(* Logix 5000 project; controller ZaxisVmpEdsSample 1769-L16ER-BB1B rev 30.11; software revision 30.00 *)

TASK MainTask (continuous, watchdog 500 ms) : MainProgram

MODULES
   Local : 1769-L16ER-BB1B (PointIO 0, rev 30.11)
      VMP_01 : vendor 1449 type 43 code 17 (Ethernet 192.168.1.193, rev 1.1, StandardDataDriven RPI 20 ms)
      VMP_02 : vendor 1449 type 43 code 17 (Ethernet 192.168.1.146, rev 1.1, StandardDataDriven RPI 20 ms)
      VMP_03 : vendor 1449 type 43 code 17 (Ethernet 192.168.1.232, rev 1.1, StandardDataDriven RPI 20 ms)
      Discrete_IO : Embedded (PointIO 1, rev 30.11, Output RPI 20 ms)
           Local:1:I.Data.0   // Green Push Btn
           Local:1:I.Data.1   // Red Push Btn
           Local:1:I   // Green Btn #2
           Local:1:O   // Green Run Light
END_MODULES

TYPE DeepSetup :
STRUCT
   Bore : REAL;   // Bore
   Gain : REAL;   // Gain
   SphericalBearing : REAL[9];   // SphericalBearing
   MotorType : DINT;   // MotorType
   PumpType : DINT;   // PumpType
   PumpNumber : DINT;   // PumpNumber
   ReadyInterlock : DINT;   // RdyInputEnabled
   HoldOnFault : DINT;   // HoldOnFault
   EthernetRunReady : DINT;   // EthSendBusy
   Triple : DINT;   // Triple
   IpDHCP : DINT;   // IpDHCP
   PumpIdentiyNumb : SINT[24];   // PumpIdentityNumber
   PumpOptions : SINT[24];   // PumpOptions
   IpAddress : SINT[16];   // IpAddress
   IpNetMask : SINT[16];   // IpNetMask
   IpGateway : SINT[16];   // IpGateWay
   SerialNumber : SINT[16];   // SerialNumber
END_STRUCT
END_TYPE

TYPE VMP_Prg :
STRUCT
   CalDispenseTime : BOOL;   // CalDispenseTime
   Direction : BOOL;   // Direction CCW
   SetShotSize : BOOL;   // Set Volume
   ContinuousRun : BOOL;   // Run Continuously
   Spare1_4 : BOOL;   // Spare Bit
   Spare1_5 : BOOL;   // Spare Bit
   Spare1_6 : BOOL;   // Spare Bit
   Spare1_7 : BOOL;   // Spare Bit
   Spare1_8 : BOOL;   // Spare Bit
   Spare1_9 : BOOL;   // Spare Bit
   Spare1_10 : BOOL;   // Spare Bit
   Spare1_11 : BOOL;   // Spare Bit
   Spare1_12 : BOOL;   // Spare Bit
   Spare1_13 : BOOL;   // Spare Bit
   Spare1_14 : BOOL;   // Spare Bit
   Spare1_15 : BOOL;   // Spare Bit
   Spare1_16 : BOOL;   // Spare Bit
   Spare1_17 : BOOL;   // Spare Bit
   Spare1_18 : BOOL;   // Spare Bit
   Spare1_19 : BOOL;   // Spare Bit
   Spare1_20 : BOOL;   // Spare Bit
   Spare1_21 : BOOL;   // Spare Bit
   Spare1_22 : BOOL;   // Spare Bit
   Spare1_23 : BOOL;   // Spare Bit
   Spare1_24 : BOOL;   // Spare Bit
   Spare1_25 : BOOL;   // Spare Bit
   Spare1_26 : BOOL;   // Spare Bit
   Spare1_27 : BOOL;   // Spare Bit
   Spare1_28 : BOOL;   // Spare Bit
   Spare1_29 : BOOL;   // Spare Bit
   Spare1_30 : BOOL;   // Spare Bit
   Spare1_31 : BOOL;   // Spare Bit
   Program : DINT;   // Program
   PullBack : DINT;   // PullBack
   InitialRPM : DINT;   // InitialRPM
   RPM : DINT;   // RPM
   FinalRPM : DINT;   // FinalRPM
   FineAdjust : DINT;   // FineAdjust
   Acceleration : DINT;   // Acceleration
   Deceleration : DINT;   // Deceleration
   LoopCycles : DINT;   // LoopCycles
   LinkedProgram : DINT;   // LinkedProgram
   LinkedTimeDelay : DINT;   // LinkedTimeDelay
   MotorCurrent : DINT;   // MotorCurrent
   Revolutions : DINT;   // Revolutions
   AprxDispenseTime : DINT;   // DispenseTime
   Volume : REAL;   // Volume
   ProgramName : STRING;   // ProgramName
END_STRUCT
END_TYPE

TYPE VMP_Setup :
STRUCT
   ReadyInterlock : BOOL;   // RdyInputEnabled
   EthernetRunReady : BOOL;   // EthSendBusy
   HoldOnFault : BOOL;   // HoldOnFault
   Spare1_3 : BOOL;   // Spare Bit
   Spare1_4 : BOOL;   // Spare Bit
   Spare1_5 : BOOL;   // Spare Bit
   Spare1_6 : BOOL;   // Spare Bit
   Spare1_7 : BOOL;   // Spare Bit
   Spare1_8 : BOOL;   // Spare Bit
   Spare1_9 : BOOL;   // Spare Bit
   Spare1_10 : BOOL;   // Spare Bit
   Spare1_11 : BOOL;   // Spare Bit
   Spare1_12 : BOOL;   // Spare Bit
   Spare1_13 : BOOL;   // Spare Bit
   Spare1_14 : BOOL;   // Spare Bit
   Spare1_15 : BOOL;   // Spare Bit
   Spare1_16 : BOOL;   // Spare Bit
   Spare1_17 : BOOL;   // Spare Bit
   Spare1_18 : BOOL;   // Spare Bit
   Spare1_19 : BOOL;   // Spare Bit
   Spare1_20 : BOOL;   // Spare Bit
   Spare1_21 : BOOL;   // Spare Bit
   Spare1_22 : BOOL;   // Spare Bit
   Spare1_23 : BOOL;   // Spare Bit
   Spare1_24 : BOOL;   // Spare Bit
   Spare1_25 : BOOL;   // Spare Bit
   Spare1_26 : BOOL;   // Spare Bit
   Spare1_27 : BOOL;   // Spare Bit
   Spare1_28 : BOOL;   // Spare Bit
   Spare1_29 : BOOL;   // Spare Bit
   Spare1_30 : BOOL;   // Spare Bit
   Spare1_31 : BOOL;   // Spare Bit
   Baud : DINT;   // Baud
   PumpNumber : DINT;   // PumpNumber
   SpareDInt0 : DINT;   // SpareDInt0
   SpareDInt1 : DINT;   // SpareDInt1
   FirmwareRev : REAL;   // FirmRev
   Bore : REAL;   // Bore
   SpareReal0 : REAL;   // SpareReal0
   SpareReal1 : REAL;   // SpareReal1
   SerialNumber : STRING;   // SerialNumber
END_STRUCT
END_TYPE

TYPE VMP_TcpIP_Cfg :
STRUCT
   Status : DINT;   // Status
   Config_Capability : DINT;   // Capability
   Config_Control : DINT;   // IfCtrl
   Path_Size : INT;   // Epath
   Path : SINT[4];   // Padd
   IP_Address : DINT;   // IPAddr
   Network_Address : DINT;   // NetAddr
   Gateway_Address : DINT;   // GateWay
   Name_Server : DINT;   // DNS1
   Name_Server_2 : DINT;   // DNS2
   Domain_Name : STRING;   // Domain
   Host_Name : STRING;   // Host
   Safety_Network_Number : SINT[6];   // Ignore
   TTL : SINT;   // TTL
   Alloc_Control : SINT;   // MultCast
   Reserved : SINT;   // Reserved
   Num_Mcast : INT;   // MultCastAlloc
   Mcast_Start_Addr : DINT;   // MultCastStart
   Selected_Acd : BOOL;   // ACD
   Acd_Activity : SINT;   // ACDState
   Remote_MAC : SINT[6];   // MACRmt
   Arp_Pdu : SINT[28];   // ARP_PDU
   EthernetIP_Quick_Connect : BOOL;   // QuickCon
   Encp_Inactivity_Timeout : INT;   // InactTimeout
END_STRUCT
END_TYPE

VAR_GLOBAL   (* controller tags *)
   Deep_Setup : DeepSetup;
   Read_Deep_Setup : BOOL;
   ReadDeepSetup : MESSAGE;
        MessageParameters(ServiceCode := 16#0001, DestinationTag := Deep_Setup, ...)
   ReadPrg : MESSAGE;
        MessageParameters(ServiceCode := 16#0001, DestinationTag := VMP_Program, ...)
   ReadSetup : MESSAGE;
        MessageParameters(ServiceCode := 16#0001, DestinationTag := VMP_Setup, ...)
   ReadTcpIp : MESSAGE;
        MessageParameters(ServiceCode := 16#0001, DestinationTag := VMP_TcpIp_Cfg, ...)
   VMP_Config : VMP_Setup;
   VMP_Program : VMP_Prg := (InitialRPM := 130, RPM := 200, FinalRPM := 130, Acceleration := 90, Deceleration := 200, LoopCycles := 1, LinkedProgram := -1, MotorCurrent := 80, AprxDispenseTime := 310, Volume := 0.1036815, ProgramName := 'Program 00');
   VMP_Setup : VMP_Setup := (Baud := 1152, PumpNumber := 1, FirmwareRev := 1.3, Bore := 0.25, SerialNumber := '123-17V3');
   VMP_TcpIp_Cfg : VMP_TcpIP_Cfg := (Status := 16#0000_0001, Config_Capability := 16#0000_0034, Path_Size := 3, Path[0] := 16#f6, Path[2] := 16#24, Path[3] := 16#01, IP_Address := 16#c0a8_a866, Network_Address := 16#ffff_ff00, Gateway_Address := 16#c0a8_0101);
   VMP_TcpIp_Read : BOOL;
   VMP_TcpIp_Write : BOOL;
   WriteDeepSetup : MESSAGE;
        MessageParameters(ServiceCode := 16#0002, LocalElement := Deep_Setup, ...)
   WritePrg : MESSAGE;
        MessageParameters(ServiceCode := 16#0002, LocalElement := VMP_Program, ...)
   WritePrg_02 : MESSAGE;
        MessageParameters(ServiceCode := 16#0002, LocalElement := VMP_Program, ...)
   WritePrg_03 : MESSAGE;
        MessageParameters(ServiceCode := 16#0002, LocalElement := VMP_Setup, ...)
   WriteSetup : MESSAGE;
        MessageParameters(ServiceCode := 16#0002, LocalElement := VMP_Setup, ...)
   WriteSetup_02 : MESSAGE;
        MessageParameters(ServiceCode := 16#0002, LocalElement := VMP_Setup, ...)
   WriteSetup_03 : MESSAGE;
        MessageParameters(ServiceCode := 16#0002, LocalElement := VMP_Setup, ...)
   WriteTcpIp : MESSAGE;
        MessageParameters(ServiceCode := 16#0002, LocalElement := VMP_TcpIp_Cfg, ...)
END_VAR

PROGRAM MainProgram   (* main routine MainRoutine *)
VAR
   Fault : ALIAS FOR VMP_01:I.Disp_Motor_Fault;
   Pmp_ReadyToRun : ALIAS FOR VMP_01:I.Ready_to_Run;   // VMP is read to run
   VMP_Prg_Read : BOOL;
   VMP_Prg_Write : BOOL := 1;
   VMP_Setup_Read : BOOL;
   VMP_Setup_Write : BOOL;
   Write_Deep_Setup : BOOL;
END_VAR

ROUTINE MainRoutine   (* ladder *)
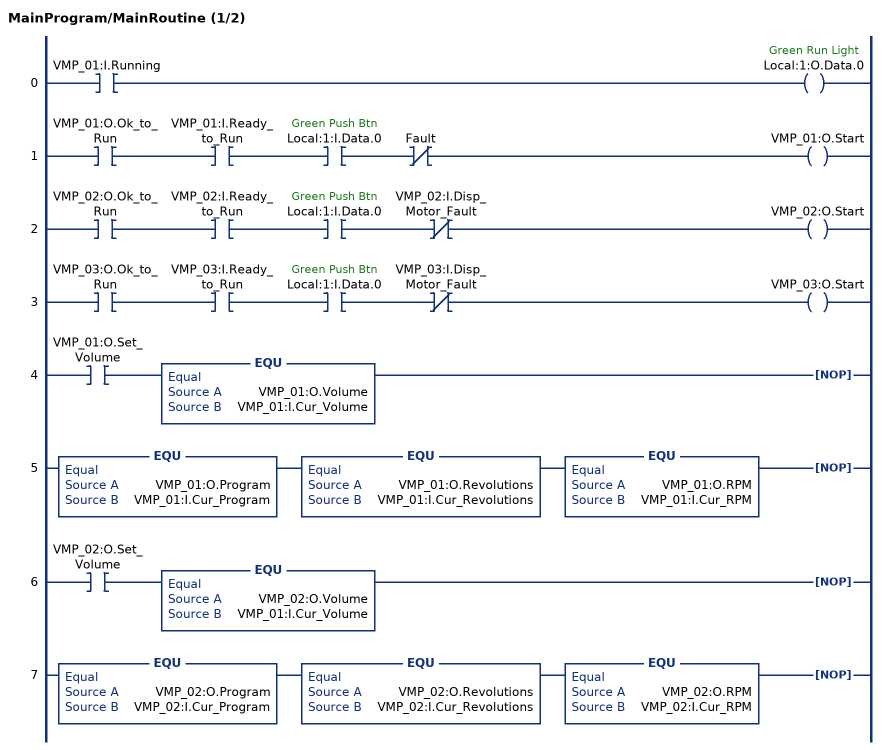
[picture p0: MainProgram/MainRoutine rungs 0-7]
   0: XIC(VMP_01:I.Running)OTE(Local:1:O.Data.0);
   1: XIC(VMP_01:O.Ok_to_Run)XIC(VMP_01:I.Ready_to_Run)XIC(Local:1:I.Data.0)XIO(Fault)OTE(VMP_01:O.Start);
   2: XIC(VMP_02:O.Ok_to_Run)XIC(VMP_02:I.Ready_to_Run)XIC(Local:1:I.Data.0)XIO(VMP_02:I.Disp_Motor_Fault)OTE(VMP_02:O.Start);
   3: XIC(VMP_03:O.Ok_to_Run)XIC(VMP_03:I.Ready_to_Run)XIC(Local:1:I.Data.0)XIO(VMP_03:I.Disp_Motor_Fault)OTE(VMP_03:O.Start);
   4: XIC(VMP_01:O.Set_Volume)EQU(VMP_01:O.Volume,VMP_01:I.Cur_Volume)NOP();
   5: EQU(VMP_01:O.Program,VMP_01:I.Cur_Program)EQU(VMP_01:O.Revolutions,VMP_01:I.Cur_Revolutions)EQU(VMP_01:O.RPM,VMP_01:I.Cur_RPM)NOP();
   6: XIC(VMP_02:O.Set_Volume)EQU(VMP_02:O.Volume,VMP_01:I.Cur_Volume)NOP();
   7: EQU(VMP_02:O.Program,VMP_02:I.Cur_Program)EQU(VMP_02:O.Revolutions,VMP_02:I.Cur_Revolutions)EQU(VMP_02:O.RPM,VMP_02:I.Cur_RPM)NOP();
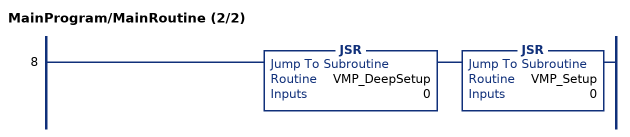
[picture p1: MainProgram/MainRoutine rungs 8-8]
   8: JSR(VMP_DeepSetup,0)JSR(VMP_Setup,0);
END_ROUTINE

ROUTINE VMP_DeepSetup   (* ladder *)
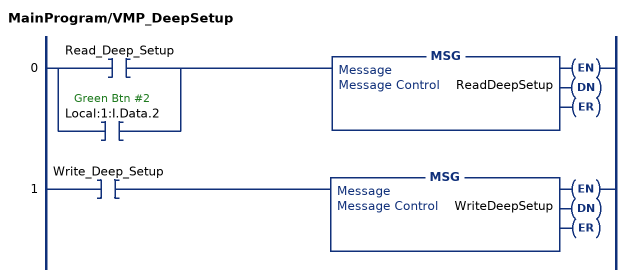
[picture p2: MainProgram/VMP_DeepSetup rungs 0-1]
   0: [XIC(Read_Deep_Setup) ,XIC(Local:1:I.Data.2) ]MSG(ReadDeepSetup);
   1: XIC(Write_Deep_Setup)MSG(WriteDeepSetup);
END_ROUTINE

ROUTINE VMP_Setup   (* ladder *)
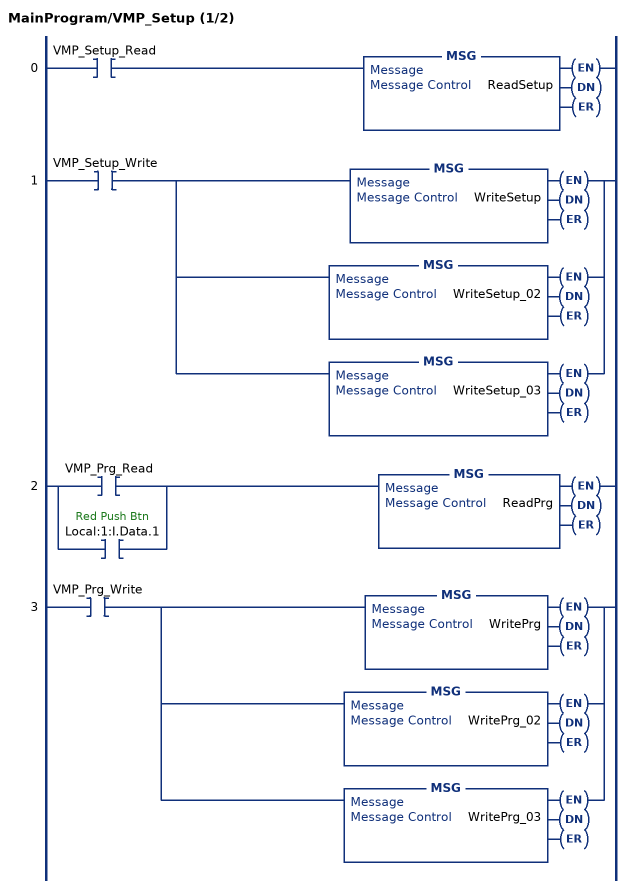
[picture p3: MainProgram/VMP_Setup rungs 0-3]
   0: XIC(VMP_Setup_Read)MSG(ReadSetup);
   1: XIC(VMP_Setup_Write)[MSG(WriteSetup) ,MSG(WriteSetup_02) ,MSG(WriteSetup_03) ];
   2: [XIC(VMP_Prg_Read) ,XIC(Local:1:I.Data.1) ]MSG(ReadPrg);
   3: XIC(VMP_Prg_Write)[MSG(WritePrg) ,MSG(WritePrg_02) ,MSG(WritePrg_03) ];
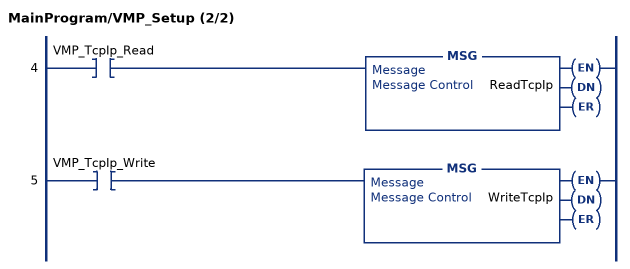
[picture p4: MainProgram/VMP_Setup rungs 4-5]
   4: XIC(VMP_TcpIp_Read)MSG(ReadTcpIp);
   5: XIC(VMP_TcpIp_Write)MSG(WriteTcpIp);
END_ROUTINE
END_PROGRAM
